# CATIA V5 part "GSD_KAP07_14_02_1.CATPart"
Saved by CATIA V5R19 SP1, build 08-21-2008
Part number: GSD_KAP07_14_02
Definition: Beispielmodell für die Funktion Eckenverrundung / EdgeFillet - Verrundung begrenzen.
Description: CATIA V5 Flächenmodellierung  Copyright (c) 2009 Maik Hertha IT Consultants
Bounding box of the stored display mesh (mm): x -56.661 to 55.861, y -41.128 to 65.964, z -10 to 30
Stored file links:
  \GSD_BUCH_UEBUNG\GSD_KAP07_14_02_1.CATPart
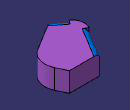
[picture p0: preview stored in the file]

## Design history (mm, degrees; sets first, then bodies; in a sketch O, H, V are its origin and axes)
AxisSystem1 "Absolute Axis System": origin (0, 0, 0), X (1, 0, 0), Y (0, 1, 0), Z (0, 0, 1)
Set1 "Edge Support"
  Plane1: type Equation, A 0, B 0, C 1, Length -10
  Point1: type OnPlane, Support Plane1, Direction (1, 0, 0), H 10, V 10
  Sketch1 on Plane1, origin (10, 10, -10), H (0, 1, 0), V (-1, 0, 0)
    line L1 (-51.1279, 33.3631) -> (-33.587, 56.515)
    arc A1 centre (-13.1715, 41.0472) radius 25.6134 from (-33.587, 56.515) to (0.0896, 62.9604) cw
    line L2 (0.0896, 62.9604) -> (55.9639, 29.1473)
    line L3 (55.9639, 29.1473) -> (55.9639, -32.6844)
    line L4 (55.9639, -32.6844) -> (35.6076, -42.197)
    arc A2 centre (19.1105, -6.8942) radius 38.9672 from (35.6076, -42.197) to (-11.5309, -30.968) cw
    line L5 (-11.5309, -30.968) -> (-51.1279, 33.3631)
    curve C1
    construction line L6 (-0.9087, -48.1015) -> (-25.9518, -8.5836)
    angle L5 L6 = 0.75
    tangency: A1 L1, L2 A1, A2 L4, L6 A2
    vertical: L3 V
  Split1: ToCut Plane1, Cutting Sketch1.C1
  Extrude1: Lim1 40, Lim2 0, Element1 Split1, Direction Plane1
Set2 "Edge 1"
  DatumSurface1: linked copy from another document
  Fillet1: radius 10, on edge [face of DatumSurface1 | face of DatumSurface1]
Body1 (main body)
